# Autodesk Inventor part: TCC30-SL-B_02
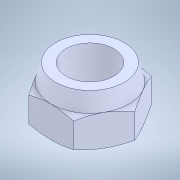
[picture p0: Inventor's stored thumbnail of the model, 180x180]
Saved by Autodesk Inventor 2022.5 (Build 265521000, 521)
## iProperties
Created: 2023-09
Part Number: TCC30-SL-B_02
Material: 一般
Document SubType Name: Modeling
Designer: ImaoCorp
Density: 1 g/cm^3
Appearance: 既定
Author: ImaoCorp
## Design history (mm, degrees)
feature "TCC30-SL-B_02"
node "ソリッド1"
